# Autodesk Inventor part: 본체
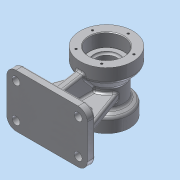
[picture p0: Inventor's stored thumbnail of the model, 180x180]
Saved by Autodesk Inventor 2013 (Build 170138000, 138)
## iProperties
Created: 2015-08
Part Number: 본체
Material: 알루미늄 6061
Document SubType Name: Modeling
Designer: Administrator
Mass: 1059.11 g
Surface Area: 750.406 cm^2
Volume: 390.815 cm^3
Density: 2.71 g/cm^3
Author: Administrator
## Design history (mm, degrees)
sketch "스케치1"
  geometry: L1 (14, 0)-(108, 0); L2 (122, 14)-(122, 66); L3 (108, 80)-(14, 80); L4 (0, 66)-(0, 14); C1 r 6 at (14, 66); C2 r 6 at (108, 66); C3 r 6 at (108, 14); C4 r 6 at (14, 14); A1 r 14 centre (14, 66) between (14, 80) and (0, 66); A2 r 14 centre (108, 66) between (122, 66) and (108, 80); A3 r 14 centre (108, 14) between (108, 0) and (122, 14); A4 r 14 centre (14, 14) between (0, 14) and (14, 0); 4 further points
  constraints: 8 centre point, 8 end point, 8 point on circle, 8 point on line, 8 tangent, 4 coincident, 3 equal radius, 2 parallel, 1 horizontal, 1 perpendicular
  dimensions: "d0" = 122 distance of point (0, 80) point (122, 80); "d1" = 80 distance of point (122, 80) point (122, 0); "d2" = 14 radius of A1; "d3" = 12 diameter of C1; "d4" = 12 diameter of C2; "d5" = 12 diameter of C3; "d6" = 12 diameter of C4
extrude "돌출1" new body sketch "스케치1" distance "d7" = 12; taper "d8" = 0 deg
node "작업 평면1"
sketch "스케치2"
  geometry: L1 (108, 12)-(108, 0) reference; L2 (108, 0)-(-14, 0) reference; L3 (-14, 0)-(-14, 12) reference; L4 (-14, 12)-(108, 12) reference; L5 (-14, 12)-(-4, 12); L6 (-4, 12)-(26.782, 96.572); L7 (47, 0)-(47, 33.484); L8 (47, 12)-(23, 12); L9 (23, 12)-(23, 30); L10 (23, 30)-(23, 24); L11 (23, 24)-(23, 24); L12 (29, 30)-(29, 36); L13 (23, 42)-(23, 42); L14 (17, 36)-(17, 30); L15 (23, 24)-(23, 24); L16 (77, 36)-(77, 30); L17 (65, 30)-(65, 36); L18 (71, 42)-(71, 42); L19 (98, 12)-(67.218, 96.572); L20 (71, 30)-(71, 24); L21 (71, 24)-(71, 24); L22 (71, 24)-(71, 24); L23 (71, 12)-(71, 30); L24 (26.782, 96.572)-(67.218, 96.572); L25 (-4, 12)-(98, 12); A1 r 6 centre (23, 36) between (29, 36) and (23, 42); A2 r 6 centre (23, 36) between (23, 42) and (17, 36); A3 r 6 centre (23, 30) between (17, 30) and (23, 24); A4 r 6 centre (23, 30) between (23, 24) and (29, 30); A5 r 6 centre (71, 30) between (71, 24) and (77, 30); A6 r 6 centre (71, 36) between (71, 42) and (65, 36); A7 r 6 centre (71, 36) between (77, 36) and (71, 42); A8 r 6 centre (71, 30) between (65, 30) and (71, 24); 8 further points
  constraints: 42 end point, 21 point on line, 21 symmetric about line, 16 point on circle, 8 centre point, 8 tangent, 5 perpendicular, 3 equal radius, 3 parallel, 2 midpoint, 4 other
  dimensions: "d9" = 10 distance of L3.end L5.end; "d10" = 90 distance of L5.end L6.end; "d11" = 110 deg angle of L6 L5; "d12" = 24 distance of L8.start L8.end; "d13" = 18 distance of L8.end L9.end; "d14" = 6 distance of L9.end L10.end; "d15" = 6 distance of L10.end point (29, 24); "d16" = 18 distance of point (29, 24) point (29, 42); "d17" = 12 distance of point (29, 42) point (17, 42); "d18" = 18 distance of point (17, 42) point (17, 24); "d19" = 6 radius of A1
extrude "돌출2" join sketch "스케치2" stored distance "d20" = 12; taper "d21" = 0 deg
node "작업 평면2"
extrude "돌출3" join sketch "스케치3" stored distance "d26" = 12; taper "d27" = 0 deg
sketch "스케치5"
  geometry: L1 (94, 0)-(0, 0) reference; L2 (0, 0)-(0, 12) reference; L3 (47, 0)-(47, 90); C1 r 35 at (47, 90); 1 further point
  constraints: 2 end point, 1 centre point, 1 coincident, 1 midpoint, 1 parallel
  dimensions: "d38" = 90 distance of L3.start L3.end; "d39" = 70 diameter of C1
extrude "돌출4" join sketch "스케치5" distance "d40" = 20; taper "d41" = 0 deg
sketch "스케치6"
  geometry: L1 (-108, 12)-(-94, 12) reference; L2 (-94, 12)-(-53, 12) reference; L3 (-53, 12)-(-53, 55.518) reference; L4 (-41, 80.937)-(-41, 55.518) reference; L5 (-53, 80.937)-(-41, 80.937) reference; L6 (-53, 55.518)-(-53, 80.937) reference; L7 (-108, 0)-(-108, 12) reference; L8 (-94, 0)-(-108, 0) reference; L9 (-94, 12)-(-94, 0) reference; L10 (-41, 55.518)-(-41, 12) reference; L11 (-41, 12)-(0, 12) reference; L12 (0, 12)-(0, 0) reference; L13 (0, 0)-(-94, 0) reference; L14 (0, 12)-(14, 12) reference; L15 (14, 12)-(14, 0) reference; L16 (14, 0)-(0, 0) reference; C1 r 26 at (-47, 90); A1 r 35 centre (-47, 90) between (-41, 55.518) and (-53, 55.518) reference
  constraints: 1 centre point, 1 coincident
  dimensions: "d42" = 52 diameter of C1
extrude "돌출5" join sketch "스케치6" distance "d43" = 70; taper "d44" = 0 deg
sketch "스케치7"
  geometry: C1 r 26 at (0, 0) reference; C2 r 40 at (0, 0); 1 further point
  constraints: 1 centre point, 1 coincident
  dimensions: "d45" = 80 diameter of C2
extrude "돌출6" join sketch "스케치7" distance "d46" = 20; taper "d47" = 0 deg
sketch "스케치8"
  geometry: L1 (-4, 55)-(-14, 55) reference; L2 (-14, 55)-(-14, 125) reference; L3 (-14, 125)-(6, 125) reference; L4 (6, 125)-(6, 116) reference; L5 (6, 116)-(56, 116) reference; L6 (56, 116)-(56, 130) reference; L7 (56, 130)-(76, 130) reference; L8 (76, 130)-(76, 50) reference; L9 (76, 50)-(62.7, 50) reference; L10 (62.7, 50)-(56, 12) reference; L11 (56, 12)-(66, 12) reference; L12 (66, 12)-(66, 0) reference; L13 (66, 0)-(-14, 0) reference; L14 (-14, 0)-(-14, 12) reference; L15 (-14, 12)-(-4, 12) reference; L16 (-4, 12)-(-4, 55) reference; L17 (6, 125)-(11.196, 116); L18 (6, 116)-(6, 125); L19 (6, 116)-(11.196, 116); L20 (56, 130)-(39.315, 116); L21 (39.315, 116)-(56, 116); L22 (56, 116)-(56, 130); L23 (-14, 90)-(21.602, 90)
  constraints: 14 end point, 2 collinear, 2 point on line, 1 midpoint, 1 perpendicular
  dimensions: "d49" = 60 deg angle of L19 L17; "d50" = 40 deg angle of L5 L20
revolve "회전2" sketch "스케치8" stored, may be unused: angle "d51" = 90 deg
sketch "스케치9"
  geometry: C1 r 40 at (0, 0) reference; C2 r 16 at (0, 0); 1 further point
  constraints: 1 centre point, 1 coincident
  dimensions: "d52" = 32 diameter of C2
extrude "돌출7" cut sketch "스케치9" distance "d54" = 90; taper "d55" = 0 deg
sketch "스케치10"
  geometry: C1 r 16 at (0, 0) reference; C2 r 40 at (0, 0) reference; C3 r 19 at (0, 0); 1 further point
  constraints: 1 centre point, 1 coincident
  dimensions: "d56" = 38 diameter of C3
extrude "돌출8" cut sketch "스케치10" distance "d57" = 23; taper "d58" = 0 deg
sketch "스케치11"
  geometry: C1 r 19 at (0, 0) reference; C2 r 40 at (0, 0) reference; C3 r 26 at (0, 0); 1 further point
  constraints: 1 centre point, 1 coincident
  dimensions: "d59" = 52 diameter of C3
extrude "돌출9" cut sketch "스케치11" distance "d60" = 20; taper "d61" = 0 deg
sketch "스케치12"
  geometry: C1 r 16 at (0, 0) reference; C2 r 35 at (0, 0) reference; C3 r 20 at (0, 0); 1 further point
  constraints: 1 centre point, 1 coincident
  dimensions: "d62" = 40 diameter of C3
extrude "돌출10" cut sketch "스케치12" distance "d63" = 20; taper "d64" = 0 deg
sketch "스케치13"
  geometry: L1 (0, 0)-(0, 33); C1 r 40 at (0, 0) reference; 1 further point
  constraints: 2 end point, 1 vertical
  dimensions: "d65" = 33 distance of L1.start L1.end
hole "구멍1" sketch "스케치13" at (0, 33) diameter "d66" = 3.242; stored, may be unused: countersink angle "d70" = 90 deg, drill point angle "d72" = 118 deg; dims "d67" = 10, "d68" = 4, "d69" = 2, "d71" = 13
sketch "스케치14"
  geometry: L1 (0, 0)-(0, 27); C1 r 35 at (0, 0) reference; 1 further point
  constraints: 2 end point, 1 vertical
  dimensions: "d76" = 27 distance of L1.start L1.end
hole "구멍2" sketch "스케치14" at (0, 27) diameter "d77" = 3.242; stored, may be unused: countersink angle "d81" = 90 deg, drill point angle "d83" = 118 deg; dims "d78" = 10, "d79" = 4, "d80" = 2, "d82" = 13
fillet "모깎기1" dims "d90" = 5
fillet "모깎기2" dims "d91" = 3
chamfer "모따기1" distance "d92" = 1; stored, may be unused: second distance "d93" = 2, angle "d94" = 45 deg
fillet "모깎기3" dims "d95" = 0.3
sketch "스케치15"
  geometry: L1 (3.113, 55.518)-(-4, 55.518) reference; L2 (-4, 55.518)-(-14, 55.518) reference; L3 (-14, 55.518)-(-14, 69.875) reference; L4 (-13, 70.921)-(5.7, 70.921) reference; L5 (6, 71.236)-(6, 75.168) reference; L6 (6, 75.168)-(53, 75.168) reference; L7 (56, 71.972)-(56, 65.01) reference; L8 (56.3, 64.702)-(75, 64.702) reference; L9 (76, 63.675)-(76, 50.453) reference; L10 (76, 50.453)-(62.78, 50.453) reference; L11 (62.78, 50.453)-(56, 12) reference; L12 (56, 12)-(66, 12) reference; L13 (66, 12)-(66, 0) reference; L14 (66, 0)-(-14, 0) reference; L15 (-14, 0)-(-14, 12) reference; L16 (-14, 12)-(-4, 12) reference; L17 (-4, 12)-(20, 12) reference; L18 (20, 12)-(20, 64.702) reference; L19 (20, 64.702)-(14.083, 64.702) reference; L20 (-4, 12)-(-4, 55.518) reference; L21 (62.78, 50.453)-(57.82, 50.453) reference; L22 (37.496, 64.702)-(32, 64.702) reference; L23 (32, 64.702)-(32, 12) reference; L24 (32, 12)-(56, 12) reference; L25 (14.083, 115.298)-(37.496, 115.298) reference; L26 (57.82, 129.547)-(76, 129.547) reference; L27 (76, 129.547)-(76, 116.325) reference; L28 (75, 115.298)-(56.3, 115.298) reference; L29 (56, 114.99)-(56, 108.028) reference; L30 (53, 104.832)-(6, 104.832) reference; L31 (6, 104.832)-(6, 108.764) reference; L32 (5.7, 109.079)-(-13, 109.079) reference; L33 (-14, 110.125)-(-14, 124.482) reference; L34 (-14, 124.482)-(3.113, 124.482) reference; L35 (-4, 12)-(12, 12); L36 (12, 12)-(12, 36); 9 further points
  constraints: 4 end point, 1 coincident, 1 perpendicular, 1 point on line, 23 other
  dimensions: "d96" = 16 distance of L16.end L35.end; "d97" = 24 distance of L35.end L36.end
feature "엠보싱1" sketch "스케치15" dims "d0" = 122, "d1" = 80, "d2" = 14, "d3" = 12, "d4" = 12, "d5" = 12, "d6" = 12, "d98" = 0.5, "d99" = 0
fillet "모깎기4" dims "d100" = 3
fillet "모깎기5" dims "d101" = 3
fillet "모깎기6" dims "d102" = 3
node "솔리드1"
pattern_circular "원형 패턴2" dims angle "d85" = 360 deg
pattern_circular "원형 패턴3" dims angle "d88" = 360 deg
node "절단 모서리 투영1"
node "절단 모서리 투영12"
node "절단 모서리 투영13"
node "절단 모서리 투영14"
other parameters: "d24" = 80 deg
